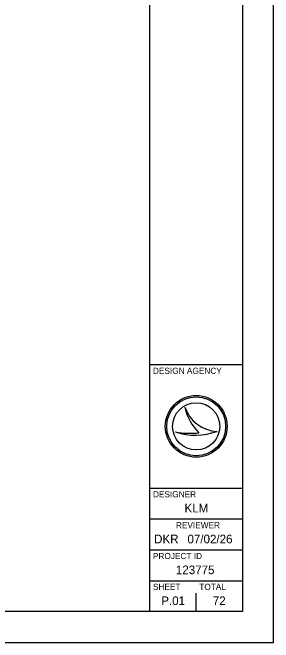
# Model space of a CAD drawing. Extents: x 0 to 34, y 0 to 22.
# Drawn here: x 29.78 to 34, y 0 to 10.2 of the extents above; entities that cross this region are included whole.
import ezdxf

# ---------------------------------------------------------------- set-up
doc = ezdxf.new("R2010")
doc.units = 0
for name, color, linetype in [('SH_Border', 7, 'Continuous'), ('SH_Cut_Line', 7, 'Continuous'), ('SH_Data', 7, 'Continuous')]:
    doc.layers.add(name, color=color, linetype=linetype)

msp = doc.modelspace()

# ---------------------------------------------------------------- linework, layer by layer
at = {"layer": 'SH_Border'}
for p, q in [((32, 0.5), (32, 21.5)), ((32, 4.5), (33.5, 4.5)), ((32, 2.5), (33.5, 2.5)), ((32, 2), (33.5, 2)), ((32, 1.5), (33.5, 1.5)), ((32, 1), (33.5, 1))]:
    msp.add_line(p, q, dxfattribs=at)
msp.add_lwpolyline([(1.5, 21.5), (33.5, 21.5), (33.5, 0.5), (1.5, 0.5)], close=True, dxfattribs=at)
at = {"layer": 'SH_Cut_Line'}
msp.add_lwpolyline([(0, 0), (34, 0), (34, 22), (0, 22)], close=True, dxfattribs=at)
at = {"layer": 'SH_Data'}
for p, q in [((32.567, 3.81), (32.567, 3.81)), ((32.75, 3.5), (32.75, 3.5)), ((32.417, 3.41), (32.417, 3.41)), ((33.087, 3.419), (33.087, 3.419)), ((32.75, 0.5), (32.75, 0.8)), ((32.375, 0.675), (32.375, 0.675))]:
    msp.add_line(p, q, dxfattribs=at)
for radius in [0.5, 0.477, 0.477, 0.382]:
    msp.add_circle((32.75, 3.5), radius, dxfattribs=at)
for centre, radius, start, end in [((33.116, 3.998), 0.58, 198.9257, 198.9319), ((33.347, 3.97), 0.796, 191.6379, 191.6421), ((33.116, 3.998), 0.58, 198.9319, 267.1657), ((33.347, 3.97), 0.796, 191.6421, 226.0947), ((32.739, 4.37), 1.013, 251.4576, 290.0832), ((32.648, 4.654), 1.266, 259.4964, 259.4995), ((32.739, 4.37), 1.013, 251.4527, 251.4576), ((32.648, 4.654), 1.266, 259.4995, 276.6672)]:
    msp.add_arc(centre, radius, start, end, dxfattribs=at)

# ---------------------------------------------------------------- texts
for s, height, p in [('DESIGN AGENCY', 0.1, (32.05, 4.35)), ('DESIGNER', 0.1, (32.05, 2.35)), ('KLM', 0.14, (32.561, 2.105)), ('REVIEWER', 0.1, (32.422, 1.85)), ('DKR', 0.14, (32.069, 1.605)), ('07/02/26', 0.14, (32.609, 1.605)), ('PROJECT ID', 0.1, (32.05, 1.35)), ('123775', 0.14, (32.421, 1.105)), ('SHEET', 0.1, (32.05, 0.85)), ('TOTAL', 0.1, (32.8, 0.85)), ('P.01', 0.14, (32.184, 0.605)), ('72', 0.14, (33.019, 0.605))]:
    msp.add_text(s, height=height, dxfattribs=at).set_placement(p)

doc.saveas('drawing.dxf')
